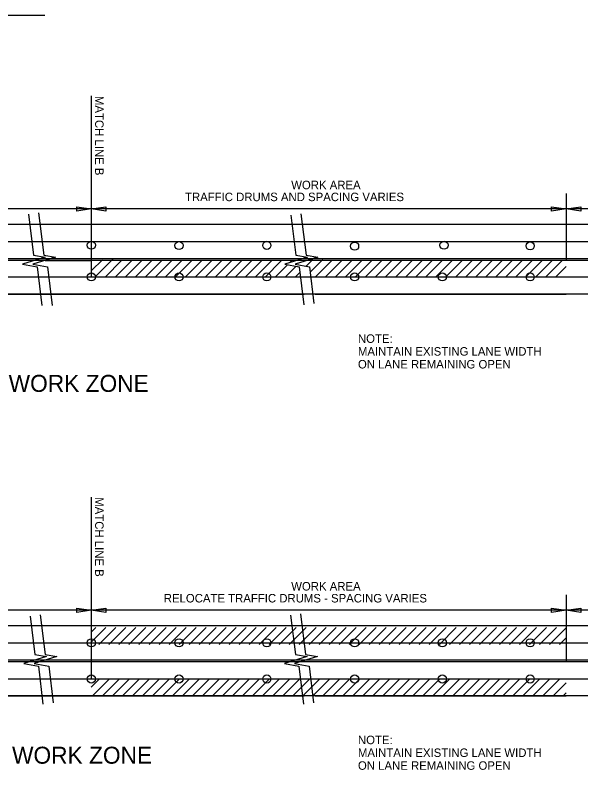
# Model space of a CAD drawing. Extents: x 1930579 to 1938013, y 596452 to 597673.
# Drawn here: x 1934133 to 1934532, y 596650 to 597183 of the extents above; entities that cross this region are included whole.
import ezdxf

# ---------------------------------------------------------------- set-up
doc = ezdxf.new("R2010")
doc.units = 0
doc.layers.add('Default', color=7, linetype='Continuous')
doc.layers.add('R_Annotation', color=7, linetype='Continuous')

msp = doc.modelspace()

# ---------------------------------------------------------------- linework, layer by layer
at = {"layer": 'Default'}
for p, q in [((1934025.15, 597183.38), (1934153.46, 597183.38)), ((1934186.36, 597126.26), (1934186.36, 597007.89)), ((1934186.36, 597058.93), (1934186.36, 597007.89)), ((1934186.36, 597058.92), (1934186.36, 597007.89)), ((1934186.36, 597058.92), (1934186.36, 596998.31)), ((1934521.71, 597057.24), (1934521.71, 597010.74)), ((1934176.06, 597044.9), (1934176.06, 597048)), ((1934176.06, 597048), (1934186.36, 597046.45)), ((1934186.36, 597046.45), (1934196.66, 597048)), ((1934196.66, 597048), (1934196.66, 597044.9)), ((1934511.4, 597044.9), (1934511.4, 597047.99)), ((1934511.4, 597047.99), (1934521.71, 597046.45)), ((1934521.71, 597046.45), (1934532.01, 597048)), ((1934532.01, 597048), (1934532.01, 597044.9)), ((1934186.36, 597046.45), (1933877.75, 597046.45)), ((1934186.36, 597046.45), (1934176.06, 597044.9)), ((1934521.71, 597046.45), (1934186.36, 597046.45)), ((1934196.66, 597044.9), (1934186.36, 597046.45)), ((1934521.71, 597046.45), (1934511.4, 597044.9)), ((1934532.01, 597044.9), (1934521.71, 597046.45)), ((1934686.11, 597046.45), (1934521.71, 597046.45)), ((1934686.11, 597035.46), (1933682.42, 597035.46)), ((1933682.42, 597023.46), (1934686.11, 597023.46)), ((1934686.11, 597011.23), (1933682.42, 597011.23)), ((1934686.11, 597010.08), (1933682.42, 597010.08)), ((1934153.67, 597010.08), (1934186.36, 597010.08)), ((1934186.37, 597009.84), (1934186.84, 597010.31)), ((1934186.54, 597002.93), (1934194.18, 597010.58)), ((1934188.98, 596998.31), (1934201.9, 597011.23)), ((1934196.05, 596998.31), (1934208.05, 597010.31)), ((1934200.98, 597010.31), (1934201.5, 597010.83)), ((1934203.13, 596998.31), (1934215.13, 597010.31)), ((1934210.2, 596998.31), (1934222.2, 597010.31)), ((1934217.27, 596998.31), (1934229.27, 597010.31)), ((1934224.34, 596998.31), (1934236.34, 597010.31)), ((1934231.41, 596998.31), (1934243.41, 597010.31)), ((1934238.48, 596998.31), (1934250.48, 597010.31)), ((1934245.55, 596998.31), (1934257.55, 597010.31)), ((1934252.62, 596998.31), (1934264.62, 597010.31)), ((1934259.69, 596998.31), (1934271.69, 597010.31)), ((1934266.76, 596998.31), (1934278.76, 597010.31)), ((1934273.84, 596998.31), (1934285.84, 597010.31)), ((1934280.91, 596998.31), (1934292.91, 597010.31)), ((1934287.98, 596998.31), (1934299.98, 597010.31)), ((1934295.05, 596998.31), (1934307.05, 597010.31)), ((1934302.12, 596998.31), (1934314.12, 597010.31)), ((1934326.6, 597008.65), (1934328.26, 597010.31)), ((1934338.17, 597006.07), (1934342.86, 597010.77)), ((1934341.14, 597001.97), (1934349.95, 597010.78)), ((1934344.55, 596998.31), (1934356.55, 597010.31)), ((1934351.62, 596998.31), (1934363.62, 597010.31)), ((1934358.69, 596998.31), (1934370.69, 597010.31)), ((1934365.76, 596998.31), (1934377.76, 597010.31)), ((1934372.83, 596998.31), (1934384.83, 597010.31)), ((1934379.9, 596998.31), (1934391.9, 597010.31)), ((1934386.97, 596998.31), (1934398.97, 597010.31)), ((1934394.04, 596998.31), (1934406.04, 597010.31)), ((1934401.12, 596998.31), (1934413.12, 597010.31)), ((1934408.19, 596998.31), (1934420.19, 597010.31)), ((1934415.26, 596998.31), (1934427.26, 597010.31)), ((1934422.33, 596998.31), (1934434.33, 597010.31)), ((1934429.4, 596998.31), (1934441.4, 597010.31)), ((1934436.47, 596998.31), (1934448.47, 597010.31)), ((1934443.54, 596998.31), (1934455.54, 597010.31)), ((1934450.61, 596998.31), (1934462.61, 597010.31)), ((1934457.68, 596998.31), (1934469.68, 597010.31)), ((1934464.75, 596998.31), (1934476.75, 597010.31)), ((1934471.83, 596998.31), (1934483.83, 597010.31)), ((1934478.9, 596998.31), (1934490.9, 597010.31)), ((1934485.97, 596998.31), (1934497.97, 597010.31)), ((1934493.04, 596998.31), (1934505.04, 597010.31)), ((1934500.11, 596998.31), (1934512.11, 597010.31)), ((1934507.18, 596998.31), (1934519.18, 597010.31)), ((1934309.19, 596998.31), (1934320.56, 597009.68)), ((1934316.26, 596998.31), (1934324.95, 597006.99)), ((1934323.33, 596998.31), (1934330.91, 597005.88)), ((1934514.25, 596998.31), (1934521.69, 597005.75)), ((1934330.36, 596998.26), (1934333.6, 597001.5)), ((1933682.42, 596998.31), (1934686.11, 596998.53)), ((1934686.11, 596986.31), (1933682.42, 596986.31)), ((1933947.06, 596986.31), (1934222.13, 596986.31)), ((1934159.38, 596986.31), (1934186.14, 596986.31)), ((1934186.14, 596986.31), (1934336.75, 596986.31)), ((1934344.4, 596986.31), (1934521.71, 596986.31)), ((1934186.36, 596842.77), (1934186.36, 596723.97)), ((1934186.36, 596775.01), (1934186.36, 596723.97)), ((1934186.36, 596775), (1934186.36, 596723.97)), ((1934186.36, 596775), (1934186.36, 596714.39)), ((1934521.71, 596773.75), (1934521.71, 596726.82)), ((1934186.36, 596762.96), (1933877.75, 596762.96)), ((1934176.06, 596761.41), (1934176.06, 596764.51)), ((1934176.06, 596764.51), (1934186.36, 596762.96)), ((1934186.36, 596762.96), (1934176.06, 596761.41)), ((1934186.36, 596762.96), (1934196.66, 596764.51)), ((1934521.71, 596762.96), (1934186.36, 596762.96)), ((1934196.66, 596761.41), (1934186.36, 596762.96)), ((1934196.66, 596764.51), (1934196.66, 596761.41)), ((1934511.4, 596761.41), (1934511.4, 596764.5)), ((1934511.4, 596764.5), (1934521.71, 596762.96)), ((1934521.71, 596762.96), (1934511.4, 596761.41)), ((1934521.71, 596762.96), (1934532.01, 596764.51)), ((1934686.11, 596762.96), (1934521.71, 596762.96)), ((1934532.01, 596761.41), (1934521.71, 596762.96)), ((1934532.01, 596764.51), (1934532.01, 596761.41)), ((1934686.11, 596751.97), (1933682.42, 596751.97)), ((1934186.36, 596740.48), (1934196.7, 596750.82)), ((1934186.36, 596747.55), (1934189.63, 596750.82)), ((1934191.77, 596738.82), (1934203.77, 596750.82)), ((1934198.84, 596738.82), (1934210.84, 596750.82)), ((1934205.91, 596738.82), (1934217.91, 596750.82)), ((1934212.98, 596738.82), (1934224.98, 596750.82)), ((1934220.05, 596738.82), (1934232.05, 596750.82)), ((1934227.13, 596738.82), (1934239.13, 596750.82)), ((1934234.2, 596738.82), (1934246.2, 596750.82)), ((1934241.27, 596738.82), (1934253.27, 596750.82)), ((1934248.34, 596738.82), (1934260.34, 596750.82)), ((1934255.41, 596738.82), (1934267.41, 596750.82)), ((1934262.48, 596738.82), (1934274.48, 596750.82)), ((1934269.55, 596738.82), (1934281.55, 596750.82)), ((1934276.62, 596738.82), (1934288.62, 596750.82)), ((1934283.69, 596738.82), (1934295.69, 596750.82)), ((1934290.76, 596738.82), (1934302.76, 596750.82)), ((1934297.84, 596738.82), (1934309.84, 596750.82)), ((1934304.91, 596738.82), (1934316.91, 596750.82)), ((1934311.98, 596738.82), (1934323.98, 596750.82)), ((1934319.05, 596738.82), (1934331.05, 596750.82)), ((1934326.12, 596738.82), (1934338.12, 596750.82)), ((1934333.19, 596738.82), (1934345.19, 596750.82)), ((1934340.26, 596738.82), (1934352.26, 596750.82)), ((1934347.33, 596738.82), (1934359.33, 596750.82)), ((1934354.4, 596738.82), (1934366.4, 596750.82)), ((1934361.48, 596738.82), (1934373.48, 596750.82)), ((1934368.55, 596738.82), (1934380.55, 596750.82)), ((1934375.62, 596738.82), (1934387.62, 596750.82)), ((1934382.69, 596738.82), (1934394.69, 596750.82)), ((1934389.76, 596738.82), (1934401.76, 596750.82)), ((1934396.83, 596738.82), (1934408.83, 596750.82)), ((1934403.9, 596738.82), (1934415.9, 596750.82)), ((1934410.97, 596738.82), (1934422.97, 596750.82)), ((1934418.04, 596738.82), (1934430.04, 596750.82)), ((1934425.12, 596738.82), (1934437.12, 596750.82)), ((1934432.19, 596738.82), (1934444.19, 596750.82)), ((1934439.26, 596738.82), (1934451.26, 596750.82)), ((1934446.33, 596738.82), (1934458.33, 596750.82)), ((1934453.4, 596738.82), (1934465.4, 596750.82)), ((1934460.47, 596738.82), (1934472.47, 596750.82)), ((1934467.54, 596738.82), (1934479.54, 596750.82)), ((1934474.61, 596738.82), (1934486.61, 596750.82)), ((1934481.68, 596738.82), (1934493.68, 596750.82)), ((1934488.75, 596738.82), (1934500.75, 596750.82)), ((1934495.83, 596738.82), (1934507.83, 596750.82)), ((1934502.9, 596738.82), (1934514.9, 596750.82)), ((1934509.97, 596738.82), (1934521.97, 596750.82)), ((1934517.04, 596738.82), (1934521.71, 596743.49)), ((1933682.42, 596739.97), (1934686.11, 596739.97)), ((1934686.11, 596727.74), (1933682.42, 596727.74)), ((1934686.11, 596726.59), (1933682.42, 596726.59)), ((1933682.42, 596714.39), (1934686.11, 596714.39)), ((1934186.36, 596708.62), (1934192.13, 596714.39)), ((1934187.2, 596702.39), (1934199.2, 596714.39)), ((1934194.27, 596702.39), (1934206.27, 596714.39)), ((1934201.34, 596702.39), (1934213.34, 596714.39)), ((1934208.41, 596702.39), (1934220.41, 596714.39)), ((1934215.48, 596702.39), (1934227.48, 596714.39)), ((1934222.55, 596702.39), (1934234.55, 596714.39)), ((1934229.62, 596702.39), (1934241.62, 596714.39)), ((1934236.69, 596702.39), (1934248.69, 596714.39)), ((1934243.76, 596702.39), (1934255.76, 596714.39)), ((1934250.84, 596702.39), (1934262.84, 596714.39)), ((1934257.91, 596702.39), (1934269.91, 596714.39)), ((1934264.98, 596702.39), (1934276.98, 596714.39)), ((1934272.05, 596702.39), (1934284.05, 596714.39)), ((1934279.12, 596702.39), (1934291.12, 596714.39)), ((1934286.19, 596702.39), (1934298.19, 596714.39)), ((1934293.26, 596702.39), (1934305.26, 596714.39)), ((1934300.33, 596702.39), (1934312.33, 596714.39)), ((1934307.4, 596702.39), (1934319.4, 596714.39)), ((1934314.48, 596702.39), (1934326.48, 596714.39)), ((1934321.55, 596702.39), (1934333.55, 596714.39)), ((1934328.62, 596702.39), (1934340.62, 596714.39)), ((1934335.69, 596702.39), (1934347.69, 596714.39)), ((1934342.76, 596702.39), (1934354.76, 596714.39)), ((1934349.83, 596702.39), (1934361.83, 596714.39)), ((1934356.9, 596702.39), (1934368.9, 596714.39)), ((1934363.97, 596702.39), (1934375.97, 596714.39)), ((1934371.04, 596702.39), (1934383.04, 596714.39)), ((1934378.12, 596702.39), (1934390.12, 596714.39)), ((1934385.19, 596702.39), (1934397.19, 596714.39)), ((1934392.26, 596702.39), (1934404.26, 596714.39)), ((1934399.33, 596702.39), (1934411.33, 596714.39)), ((1934406.4, 596702.39), (1934418.4, 596714.39)), ((1934413.47, 596702.39), (1934425.47, 596714.39)), ((1934420.54, 596702.39), (1934432.54, 596714.39)), ((1934427.61, 596702.39), (1934439.61, 596714.39)), ((1934434.68, 596702.39), (1934446.68, 596714.39)), ((1934441.75, 596702.39), (1934453.75, 596714.39)), ((1934448.83, 596702.39), (1934460.83, 596714.39)), ((1934455.9, 596702.39), (1934467.9, 596714.39)), ((1934462.97, 596702.39), (1934474.97, 596714.39)), ((1934470.04, 596702.39), (1934482.04, 596714.39)), ((1934477.11, 596702.39), (1934489.11, 596714.39)), ((1934484.18, 596702.39), (1934496.18, 596714.39)), ((1934491.25, 596702.39), (1934503.25, 596714.39)), ((1934498.32, 596702.39), (1934510.32, 596714.39)), ((1934505.39, 596702.39), (1934517.39, 596714.39)), ((1934512.47, 596702.39), (1934521.71, 596711.63)), ((1934686.11, 596702.39), (1933682.42, 596702.39)), ((1933947.06, 596702.39), (1934222.13, 596702.39)), ((1934159.38, 596702.39), (1934186.14, 596702.39)), ((1934186.14, 596702.39), (1934336.75, 596702.39)), ((1934344.4, 596702.39), (1934521.71, 596702.39)), ((1934519.54, 596702.39), (1934521.71, 596704.56))]:
    msp.add_line(p, q, dxfattribs=at)
for points in [[(1934142.01, 597042.85), (1934145.63, 597013.83), (1934153.89, 597012.37), (1934137.86, 597007.52), (1934148.06, 597005.57), (1934151.35, 596978.24)], [(1934149.18, 597043.74), (1934152.91, 597013.83), (1934161.17, 597012.37), (1934145.14, 597007.52), (1934155.34, 597005.57), (1934158.64, 596978.14)], [(1934327.26, 597042.15), (1934330.8, 597013.83), (1934339.06, 597012.37), (1934323.03, 597007.52), (1934333.23, 597005.57), (1934336.45, 596978.81)], [(1934334.44, 597043.05), (1934338.09, 597013.83), (1934346.34, 597012.37), (1934330.32, 597007.52), (1934340.52, 597005.57), (1934343.63, 596979.67)], [(1934150.35, 596759.7), (1934153.85, 596731.72), (1934162.1, 596730.26), (1934146.08, 596725.4), (1934156.27, 596723.46), (1934159.39, 596697.56)], [(1934327.02, 596759.49), (1934330.49, 596731.72), (1934338.74, 596730.26), (1934322.72, 596725.4), (1934332.91, 596723.46), (1934336.13, 596696.69)], [(1934334.19, 596760.38), (1934337.77, 596731.72), (1934346.03, 596730.26), (1934330, 596725.4), (1934340.2, 596723.46), (1934343.31, 596697.56)], [(1934143.18, 596758.81), (1934146.56, 596731.72), (1934154.82, 596730.26), (1934138.79, 596725.4), (1934148.99, 596723.46), (1934152.21, 596696.69)]]:
    msp.add_lwpolyline(points, dxfattribs=at)
for centre in [(1934186.36, 597020.8), (1934248.35, 597020.56), (1934310.34, 597020.7), (1934372.33, 597020.12), (1934435.51, 597020.82), (1934496.32, 597020.33), (1934186.36, 596998.42), (1934248.35, 596998.42), (1934310.34, 596998.42), (1934372.33, 596998.42), (1934434.33, 596998.42), (1934496.32, 596998.42), (1934186.36, 596739.96), (1934248.35, 596739.96), (1934310.34, 596739.96), (1934372.33, 596739.96), (1934434.33, 596739.96), (1934496.32, 596739.96), (1934186.36, 596714.39), (1934248.35, 596714.39), (1934310.34, 596714.39), (1934372.33, 596714.39), (1934434.33, 596714.39), (1934496.32, 596714.39)]:
    msp.add_circle(centre, 2.87, dxfattribs=at)

# ---------------------------------------------------------------- texts
for s, height, rotation, p in [('MATCH LINE B', 6, 270, (1934189.06, 597126.26)), ('WORK AREA', 6, 360, (1934327.57, 597060.38)), ('TRAFFIC DRUMS AND SPACING VARIES', 6, 360, (1934252.56, 597051.95)), ('DIVERSION FOR LT. LANE WORK ZONE', 12, 360, (1933922.91, 596917.22)), ('MATCH LINE B', 6, 270, (1934189.06, 596842.77)), ('WORK AREA', 6, 360, (1934327.57, 596776.89)), ('RELOCATE TRAFFIC DRUMS - SPACING VARIES', 6, 360, (1934237.56, 596768.46)), ('DIVERSION FOR RT. LANE WORK ZONE', 12, 360, (1933922.63, 596654.55))]:
    msp.add_text(s, height=height, rotation=rotation, dxfattribs=at).set_placement(p)
at = {"layer": 'R_Annotation'}
for s, p in [('NOTE:', (1934374.7, 596951.85)), ('MAINTAIN EXISTING LANE WIDTH', (1934374.7, 596942.8)), ('ON LANE REMAINING OPEN', (1934374.7, 596933.75)), ('NOTE:', (1934374.7, 596668.36)), ('MAINTAIN EXISTING LANE WIDTH', (1934374.7, 596659.31)), ('ON LANE REMAINING OPEN', (1934374.7, 596650.26))]:
    msp.add_text(s, height=6, rotation=360, dxfattribs=at).set_placement(p)

doc.saveas('drawing.dxf')
